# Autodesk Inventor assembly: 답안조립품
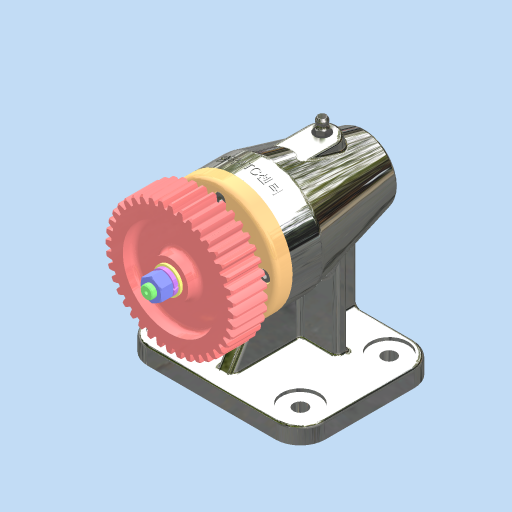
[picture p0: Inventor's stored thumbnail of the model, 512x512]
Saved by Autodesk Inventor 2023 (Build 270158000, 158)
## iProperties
Created: 2024-12
Part Number: 답안조립품
Document SubType Name: Assembly
Designer: asung
Author: asung
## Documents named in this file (15)
- C:\Users\asung\Desktop\741204V1014\답안조립품.iam
- C:\Users\asung\Desktop\741204V1014\본체.ipt
- C:\Users\asung\Documents\Inventor\그리스 니플 M6x0.75.ipt
- C:\Users\asung\Desktop\741204V1014\가져온 구성요소\스퍼기어\스퍼기어.ipt
- C:\Users\asung\Desktop\741204V1014\가져온 구성요소\스프링 와셔 M8\스프링 와셔 M8.ipt
- C:\Users\asung\Desktop\741204V1014\가져온 구성요소\실링\실링.ipt
- C:\Users\asung\Desktop\741204V1014\가져온 구성요소\앵귤러 볼 베어링 7003A\앵귤러 볼 베어링 7003A.ipt
- C:\Users\asung\Desktop\741204V1014\가져온 구성요소\앵귤러 볼 제어링 7204A\앵귤러 볼 제어링 7204A.ipt
- C:\Users\asung\Desktop\741204V1014\가져온 구성요소\오일 실 20 32 8\오일 실 20 32 8.ipt
- C:\Users\asung\Desktop\741204V1014\가져온 구성요소\육각 너트 M8\육각 너트 M8.ipt
- C:\Users\asung\Desktop\741204V1014\가져온 구성요소\육각 소켓 머리 볼트 M4x10\육각 소켓 머리 볼트 M4x10.ipt
- C:\Users\asung\Desktop\741204V1014\가져온 구성요소\축\축.ipt
- C:\Users\asung\Desktop\741204V1014\가져온 구성요소\커버\커버.ipt
- C:\Users\asung\Desktop\741204V1014\가져온 구성요소\평와셔 M8\평와셔 M8.ipt
- C:\Users\asung\Desktop\741204V1014\가져온 구성요소\평행 키 4x4x14\평행 키 4x4x14.ipt
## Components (1 placed, 1 different names)
1. 그리스 니플 M6x0.75:1
